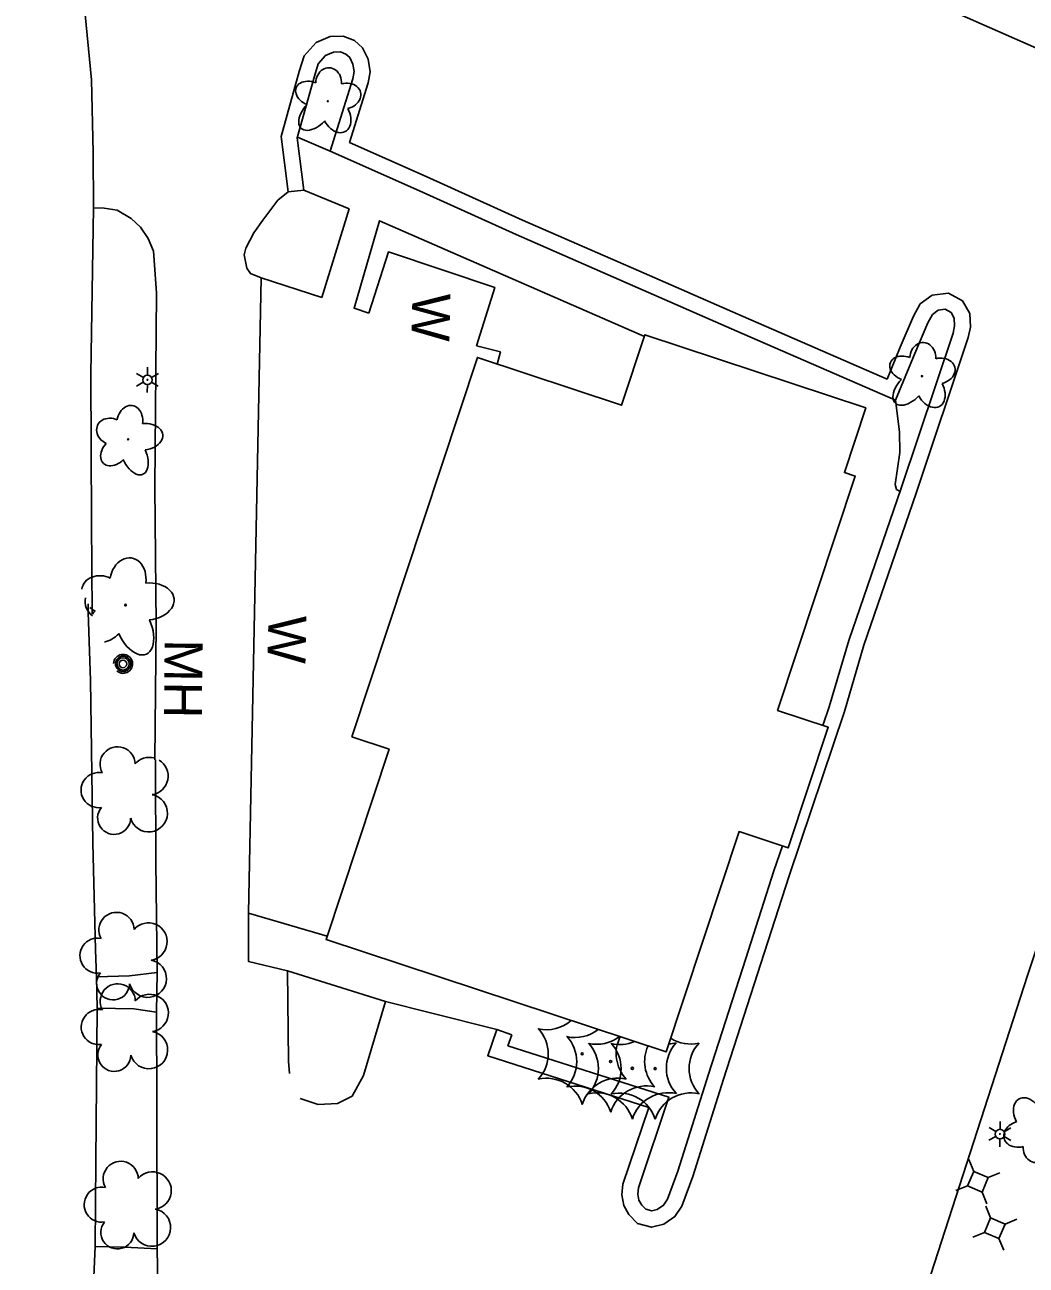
# Model space of a CAD drawing. Extents: x 588843 to 2552415, y 180129 to 269402.
# Drawn here: x 592942.9 to 593101.4, y 185566.6 to 185762.9 of the extents above; entities that cross this region are included whole.
import ezdxf

# ---------------------------------------------------------------- set-up
doc = ezdxf.new("R2010")
doc.units = 0
for name, color, linetype in [('Default', 7, 'Continuous'), ('E_BLD', 7, 'Continuous'), ('E_DWY', 7, 'Continuous'), ('E_LAND_Vegetation', 7, 'Continuous'), ('E_LTG', 7, 'Continuous'), ('E_PATH_Sidewalk', 7, 'Continuous'), ('E_RDWY', 7, 'Continuous'), ('E_UTL_AG_Bold', 7, 'Continuous'), ('E_UTL_MH', 7, 'Continuous'), ('E_UTL_MH_Text', 7, 'Continuous'), ('E_WAL', 7, 'Continuous'), ('E_WAL_Text', 7, 'Continuous'), ('Level 11', 7, 'Continuous'), ('Level 17', 7, 'Continuous'), ('Level 18', 7, 'Continuous')]:
    doc.layers.add(name, color=color, linetype=linetype)

# ---------------------------------------------------------------- blocks, each defined once
blk = doc.blocks.new('LPOL')
at = {"layer": 'Default'}
for p, q in [((-4, 0), (-1.5, 0)), ((-0.75, 1.3), (-2, 3.46)), ((0.75, 1.3), (2, 3.46)), ((1.5, 0), (4, 0)), ((-2, -3.46), (-0.75, -1.3)), ((2, -3.46), (0.75, -1.3))]:
    blk.add_line(p, q, dxfattribs=at)
for radius in [1.5, 1.5, 1.5, 0.125]:
    blk.add_circle((0, 0), radius, dxfattribs=at)
blk = doc.blocks.new('DTRE')
at = {"layer": 'Default'}
blk.add_circle((-0.18, 0), 0.183, dxfattribs=at)
for centre, major_axis, ratio in [((-1.87, 5.32), (1.36, -4.98), 0.782863), ((4.06, 2.74), (-5.27, -2.93), 0.691916), ((-5.87, 0.15), (4.93, -0.12), 0.832022), ((3.54, -3.71), (-5.01, 4.58), 0.560249), ((-2.49, -5.24), (1.8, 4.86), 0.716896)]:
    blk.add_ellipse(centre, major_axis=major_axis, ratio=ratio, start_param=1.570796, end_param=4.712389, dxfattribs=at)
blk = doc.blocks.new('PED')
at = {"layer": 'Default'}
for p, q in [((-2.5, 2.5), (-5.33, 5.33)), ((2.5, 2.5), (5.33, 5.33)), ((-2.5, -2.5), (-5.33, -5.33)), ((2.5, -2.5), (5.33, -5.33))]:
    blk.add_line(p, q, dxfattribs=at)
blk.add_lwpolyline([(-2.5, -2.5), (2.5, -2.5), (2.5, 2.5), (-2.5, 2.5)], close=True, dxfattribs=at)
blk = doc.blocks.new('W_31')
at = {"layer": 'E_WAL_Text'}
blk.add_text('W', height=12, dxfattribs=at).set_placement((-4.46, -6))
blk = doc.blocks.new('MHT')
at = {"layer": 'E_UTL_MH_Text'}
blk.add_text('MH', height=12, dxfattribs=at).set_placement((-9.81, -6))
blk = doc.blocks.new('U324')
at = {"layer": 'E_LAND_Vegetation'}
blk.add_circle((0.01, 0.01), 0.167, dxfattribs=at)
for centre, radius, start, end in [((-11.26, -0.01), 5.9, 317.2159, 42.9808), ((-5.63, 9.71), 5.9, 257.2113, 311.4886), ((11.29, 0.03), 5.9, 152.8514, 222.9808), ((-5.61, -9.76), 5.9, 17.2159, 102.9808), ((5.67, -9.75), 5.91, 77.2557, 162.9318)]:
    blk.add_arc(centre, radius, start, end, dxfattribs=at)
blk = doc.blocks.new('U325')
at = {"layer": 'E_LAND_Vegetation'}
blk.add_circle((0.01, 0.01), 0.167, dxfattribs=at)
for centre, radius, start, end in [((-11.26, -0.01), 5.9, 317.2159, 42.9808), ((-5.63, 9.71), 5.9, 257.2113, 308.6979), ((11.29, 0.03), 5.9, 155.2498, 222.9808), ((-5.61, -9.76), 5.9, 17.2159, 102.9808), ((5.67, -9.75), 5.91, 77.2557, 162.9318)]:
    blk.add_arc(centre, radius, start, end, dxfattribs=at)
blk = doc.blocks.new('U326')
at = {"layer": 'E_LAND_Vegetation'}
blk.add_circle((0.01, 0.01), 0.167, dxfattribs=at)
for centre, radius, start, end in [((-11.26, -0.01), 5.9, 317.2159, 42.9808), ((-5.63, 9.71), 5.9, 257.2113, 307.9346), ((11.29, 0.03), 5.9, 137.2159, 222.9808), ((5.63, 9.79), 5.9, 271.5766, 282.9808), ((-5.61, -9.76), 5.9, 17.2159, 102.9808), ((5.67, -9.75), 5.91, 77.2557, 162.9318)]:
    blk.add_arc(centre, radius, start, end, dxfattribs=at)
blk = doc.blocks.new('U327')
at = {"layer": 'E_LAND_Vegetation'}
blk.add_circle((0.01, 0.01), 0.167, dxfattribs=at)
for centre, radius, start, end in [((-11.26, -0.01), 5.9, 317.2159, 42.9808), ((-5.63, 9.71), 5.9, 257.2113, 293.8634), ((5.63, 9.79), 5.9, 237.739, 282.9808), ((11.29, 0.03), 5.9, 137.2159, 222.9808), ((-5.61, -9.76), 5.9, 17.2159, 102.9808), ((5.67, -9.75), 5.91, 77.2557, 162.9318)]:
    blk.add_arc(centre, radius, start, end, dxfattribs=at)

msp = doc.modelspace()

# ---------------------------------------------------------------- linework, layer by layer
at = {"layer": 'E_BLD'}
msp.add_lwpolyline([(592994.69, 185650.25), (593014.55, 185710.27), (593037.36, 185702.72), (593041.04, 185713.86), (593075.98, 185702.3), (593072.6, 185692.06), (593074.31, 185691.49), (593062.04, 185654.41), (593070.04, 185651.76), (593063.72, 185632.65), (593055.94, 185635.23), (593044.41, 185600.38), (592990.6, 185618.18), (593000.57, 185648.3), (592994.69, 185650.25)], close=True, dxfattribs=at)
at = {"layer": 'E_DWY'}
for points in [[(593073.08, 185519.95), (593085.72, 185563.37), (593101.57, 185612.44), (593116.25, 185656.35), (593130.07, 185698.66), (593137.48, 185722.33), (593127, 185748.67), (593098.2, 185761.32), (593068.93, 185774.26), (593037.36, 185788.12), (593004.66, 185802.42), (592980.13, 185813.54), (592966.01, 185781.91), (592962.98, 185775.38), (592961.51, 185773.47), (592960.45, 185773.06), (592958.78, 185772.92), (592956.88, 185773.45), (592953.94, 185774.8), (592950.49, 185776.9)], [(592984.57, 185736.46), (592983.49, 185745.22), (592986.34, 185755.51), (592987.12, 185758.02), (592989.01, 185760.13), (592991.24, 185761.06), (592993.31, 185761.14), (592995.08, 185760.42), (592996.36, 185759.28), (592997.26, 185757.48), (592997.59, 185755.47), (592997.26, 185753.76), (592994.3, 185744.3), (593006.42, 185738.93), (593021.69, 185732.02), (593040.08, 185723.97), (593056.61, 185716.76), (593079.37, 185706.85), (593081.44, 185711.89), (593083.54, 185716.82), (593084.6, 185718.75), (593086.5, 185720.13), (593089.05, 185720.47), (593091.31, 185719.22), (593092.44, 185717.21), (593092.55, 185715.06), (593092.2, 185713.44), (593083.96, 185688.78), (593075.7, 185664.73), (593072.6, 185654.26)], [(592987.05, 185736.76), (592986.03, 185745.03), (592988.74, 185754.81), (592989.34, 185756.76), (592990.49, 185758.04), (592991.79, 185758.58), (592992.87, 185758.62), (592993.74, 185758.26), (592994.34, 185757.73), (592994.85, 185756.7), (592995.05, 185755.51), (592994.83, 185754.38), (592991.25, 185742.92), (593005.4, 185736.65), (593020.68, 185729.73), (593039.08, 185721.68), (593055.61, 185714.46), (593080.71, 185703.54), (593083.74, 185710.92), (593085.8, 185715.73), (593086.52, 185717.06), (593087.45, 185717.74), (593088.56, 185717.89), (593089.48, 185717.37), (593089.97, 185716.5), (593090.04, 185715.26), (593089.79, 185714.1), (593081.59, 185689.58), (593073.32, 185665.49), (593070.2, 185654.97)], [(592987.05, 185736.76), (592984.57, 185736.46), (592982.98, 185735.19), (592980.6, 185732), (592979.16, 185729.99), (592977.88, 185727.56), (592977.65, 185726.5), (592978.07, 185724.41), (592978.61, 185723.57), (592980.3, 185722.86)], [(592953.77, 185733.95), (592955.5, 185733.9), (592957.52, 185733.59), (592959.76, 185732.25), (592961.25, 185730.89), (592962.42, 185729.11), (592963.27, 185727.07), (592963.75, 185720.51), (592963.48, 185689.76), (592963.7, 185667.96), (592963.51, 185646.61)], [(593069.21, 185652.03), (593070.2, 185654.97)], [(593072.6, 185654.26), (593063.84, 185628.25)], [(593061.46, 185629.01), (593062.79, 185632.96)], [(593063.84, 185628.25), (593059.39, 185614.37), (593053.5, 185596.08), (593048.63, 185580.65), (593046.88, 185575.94), (593045.8, 185574.31), (593044.02, 185573.12), (593042.1, 185572.62), (593039.88, 185573.22), (593038.51, 185574.62), (593037.73, 185576.04), (593037.37, 185577.75), (593037.56, 185579.42), (593041.65, 185591.58), (593016.17, 185599.75), (593017.6, 185603.9)], [(593061.46, 185629.01), (593057.01, 185615.13), (593051.12, 185596.84), (593046.26, 185581.47), (593044.64, 185577.08), (593043.99, 185576.11), (593042.98, 185575.44), (593042.11, 185575.21), (593041.19, 185575.46), (593040.54, 185576.12), (593040.1, 185576.92), (593039.9, 185577.87), (593040.01, 185578.87), (593044.83, 185593.19), (593019.37, 185601.35), (593019.96, 185603.08)], [(592984.79, 185596.93), (592984.64, 185598.91), (592984.5, 185613.18), (592978.31, 185614.69), (592978.3, 185622.31)], [(593019.96, 185603.08), (593017.6, 185603.9), (593007.09, 185606.58), (593000, 185608.33), (592996.54, 185596.66), (592994.73, 185593.37), (592992.41, 185592.18), (592989.35, 185592.05), (592986.47, 185592.99)]]:
    msp.add_lwpolyline(points, dxfattribs=at)
at = {"layer": 'E_LAND_Vegetation'}
msp.add_circle((592958.86, 185671.08), 0.128, dxfattribs=at)
for centre, major_axis, ratio, start_param, end_param in [((592959.26, 185674.96), (-0.52, -3.58), 0.782863, 1.570796, 4.712389), ((592955.25, 185672.76), (3.13, -1.45), 0.832022, 1.570796, 3.35413), ((592962.34, 185671.65), (-4.2, -0.41), 0.691916, 1.570796, 4.712389), ((592955.25, 185672.76), (3.13, -1.45), 0.832022, 4.423921, 4.712389), ((592955.91, 185668.35), (2.51, 2.62), 0.716896, 1.570796, 1.746526), ((592960.22, 185667.66), (-1.94, 4.34), 0.560249, 1.570796, 4.712389), ((592955.91, 185668.35), (2.51, 2.62), 0.716896, 3.946393, 4.712389)]:
    msp.add_ellipse(centre, major_axis=major_axis, ratio=ratio, start_param=start_param, end_param=end_param, dxfattribs=at)
at = {"layer": 'E_PATH_Sidewalk'}
for points in [[(592991.25, 185742.92), (592986.05, 185745.12)], [(592989.94, 185719.77), (592994.23, 185733.77), (592987.05, 185736.76)], [(592997.34, 185717.28), (592995.03, 185718.1), (592999.03, 185731.91), (593040.95, 185713.57)], [(593014.38, 185712.11), (593018.19, 185711.17), (593017.67, 185709.23)], [(593081.41, 185689.06), (593080.87, 185689.39), (593080.65, 185690.19), (593081.38, 185695.23), (593081.32, 185698.48), (593080.71, 185703.54)], [(592978.3, 185622.31), (592990.77, 185618.69)], [(592984.5, 185613.18), (593000, 185608.33)]]:
    msp.add_lwpolyline(points, dxfattribs=at)
at = {"layer": 'E_RDWY'}
msp.add_lwpolyline([(592943.12, 185832.1), (592942.93, 185826.17), (592943.11, 185816.4), (592945.25, 185802.49), (592947.54, 185791.67), (592950.49, 185776.9), (592952.34, 185766.21), (592953.5, 185754.21), (592953.76, 185742.73), (592953.77, 185733.95), (592953.36, 185707.64), (592953.46, 185684.24), (592953.6, 185669.72)], dxfattribs=at)
at = {"layer": 'E_UTL_MH'}
for centre, radius in [((592958.49, 185661.78), 1.22), ((592958.47, 185661.77), 0.968), ((592958.45, 185661.78), 0.605)]:
    msp.add_circle(centre, radius, dxfattribs=at)
msp.add_arc((592958.48, 185661.78), 1.5, 228.2453, 178.1318, dxfattribs=at)
at = {"layer": 'E_WAL'}
for points in [[(592997.34, 185717.28), (593000.46, 185726.98), (593017.27, 185721.37), (593014.38, 185712.11)], [(592978.3, 185622.31), (592980.3, 185722.86), (592989.94, 185719.77)]]:
    msp.add_lwpolyline(points, dxfattribs=at)
at = {"layer": 'Level 11'}
for points in [[(592952.93, 185671.3), (592952.94, 185669.95), (592953.31, 185659.17), (592953.68, 185633.46), (592954.11, 185616.52), (592954.25, 185612.24)], [(592954.25, 185612.24), (592954.38, 185607.27)], [(592954.38, 185607.27), (592954.16, 185583.08), (592954.05, 185569.55)], [(592954.05, 185569.55), (592953.81, 185563.62)]]:
    msp.add_lwpolyline(points, dxfattribs=at)
at = {"layer": 'Level 17'}
for points in [[(592963.87, 185612.93), (592963.68, 185630.44), (592963.6, 185645.28), (592963.61, 185646.6)], [(592963.87, 185612.93), (592959.51, 185612.39), (592954.25, 185612.24)], [(592963.76, 185606.65), (592963.87, 185612.93)], [(592963.76, 185606.65), (592960.2, 185607.2), (592954.38, 185607.27)], [(592963.87, 185569.21), (592963.8, 185592.88), (592963.76, 185606.65)], [(592954.05, 185569.55), (592958.77, 185569.45), (592963.87, 185569.21)], [(592964, 185563.45), (592963.87, 185569.21)]]:
    msp.add_lwpolyline(points, dxfattribs=at)
at = {"layer": 'Level 18'}
for centre, radius, start, end in [((592955.25, 185671.63), 2.78, 167.5321, 234.3494), ((592957.6, 185645.88), 2.78, 1.3946, 209.1675), ((592962.64, 185644.02), 2.97, 76.4732, 139.6575), ((592962.64, 185644.02), 2.97, 278.4237, 58.6729), ((592954.6, 185641.8), 2.78, 78.0716, 279.0826), ((592962.53, 185638.16), 2.97, 196.0745, 79.0477), ((592957.06, 185637.4), 2.61, 140.7797, 358.7123), ((592957.43, 185619.68), 2.78, 1.3946, 209.1675), ((592962.48, 185617.82), 2.97, 278.4237, 139.6575), ((592954.43, 185615.61), 2.78, 78.0716, 279.0826), ((592962.37, 185611.97), 2.97, 196.0745, 79.0477), ((592956.9, 185611.21), 2.61, 140.7797, 358.7123), ((592957.63, 185608.38), 2.78, 1.3946, 209.1675), ((592962.67, 185606.52), 2.97, 278.4237, 139.6575), ((592954.63, 185604.3), 2.78, 78.0716, 279.0826), ((592962.56, 185600.67), 2.97, 196.0745, 79.0477), ((592957.09, 185599.9), 2.61, 140.7797, 358.7123), ((592958.1, 185580.28), 2.78, 1.3946, 209.1675), ((592963.14, 185578.42), 2.97, 278.4237, 139.6575), ((592955.1, 185576.2), 2.78, 78.0716, 279.0826), ((592963.03, 185572.57), 2.97, 196.0745, 79.0477), ((592957.56, 185571.8), 2.61, 140.7797, 358.7123)]:
    msp.add_arc(centre, radius, start, end, dxfattribs=at)

# ---------------------------------------------------------------- block references
at = {"layer": 'E_LAND_Vegetation'}
for p, xscale, yscale, rotation in [((592990.87, 185750.73), 0.5000000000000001, 0.5000000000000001, -91.07016509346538), ((593084.89, 185707.23), 0.5000000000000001, 0.5000000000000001, -91.07016509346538), ((592959.35, 185697.29), 0.49999999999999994, 0.5, -23.47218538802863), ((593103.03, 185588.25), 0.5000000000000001, 0.5, 89.39188762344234)]:
    msp.add_blockref('DTRE', p, dxfattribs=dict(at, xscale=xscale, yscale=yscale, rotation=rotation))
for name, p in [('U324', (593031.1, 185600.06)), ('U325', (593035.61, 185598.83)), ('U326', (593039.04, 185597.76)), ('U327', (593042.64, 185597.72))]:
    msp.add_blockref(name, p, dxfattribs=at)
at = {"layer": 'E_LTG', "xscale": 0.5000000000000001, "yscale": 0.5, "rotation": 89.39188762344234}
for p in [(592962.33, 185706.73), (593097.22, 185587.37)]:
    msp.add_blockref('LPOL', p, dxfattribs=at)
at = {"layer": 'E_UTL_AG_Bold', "xscale": 0.4999999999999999, "yscale": 0.5, "rotation": -22.99539777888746}
for p in [(593093.72, 185579.83), (593096.4, 185572.47)]:
    msp.add_blockref('PED', p, dxfattribs=at)
at = {"layer": 'E_UTL_MH_Text', "xscale": 0.4999999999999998, "yscale": 0.49999999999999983, "rotation": -90.60811237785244}
msp.add_blockref('MHT', (592968.01, 185660.74), dxfattribs=at)
at = {"layer": 'E_WAL_Text', "xscale": 0.5000000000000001, "yscale": 0.5000000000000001, "rotation": -91.07016509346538}
for p in [(593007.21, 185718.16), (592984.43, 185667.18)]:
    msp.add_blockref('W_31', p, dxfattribs=at)

doc.saveas('drawing.dxf')
